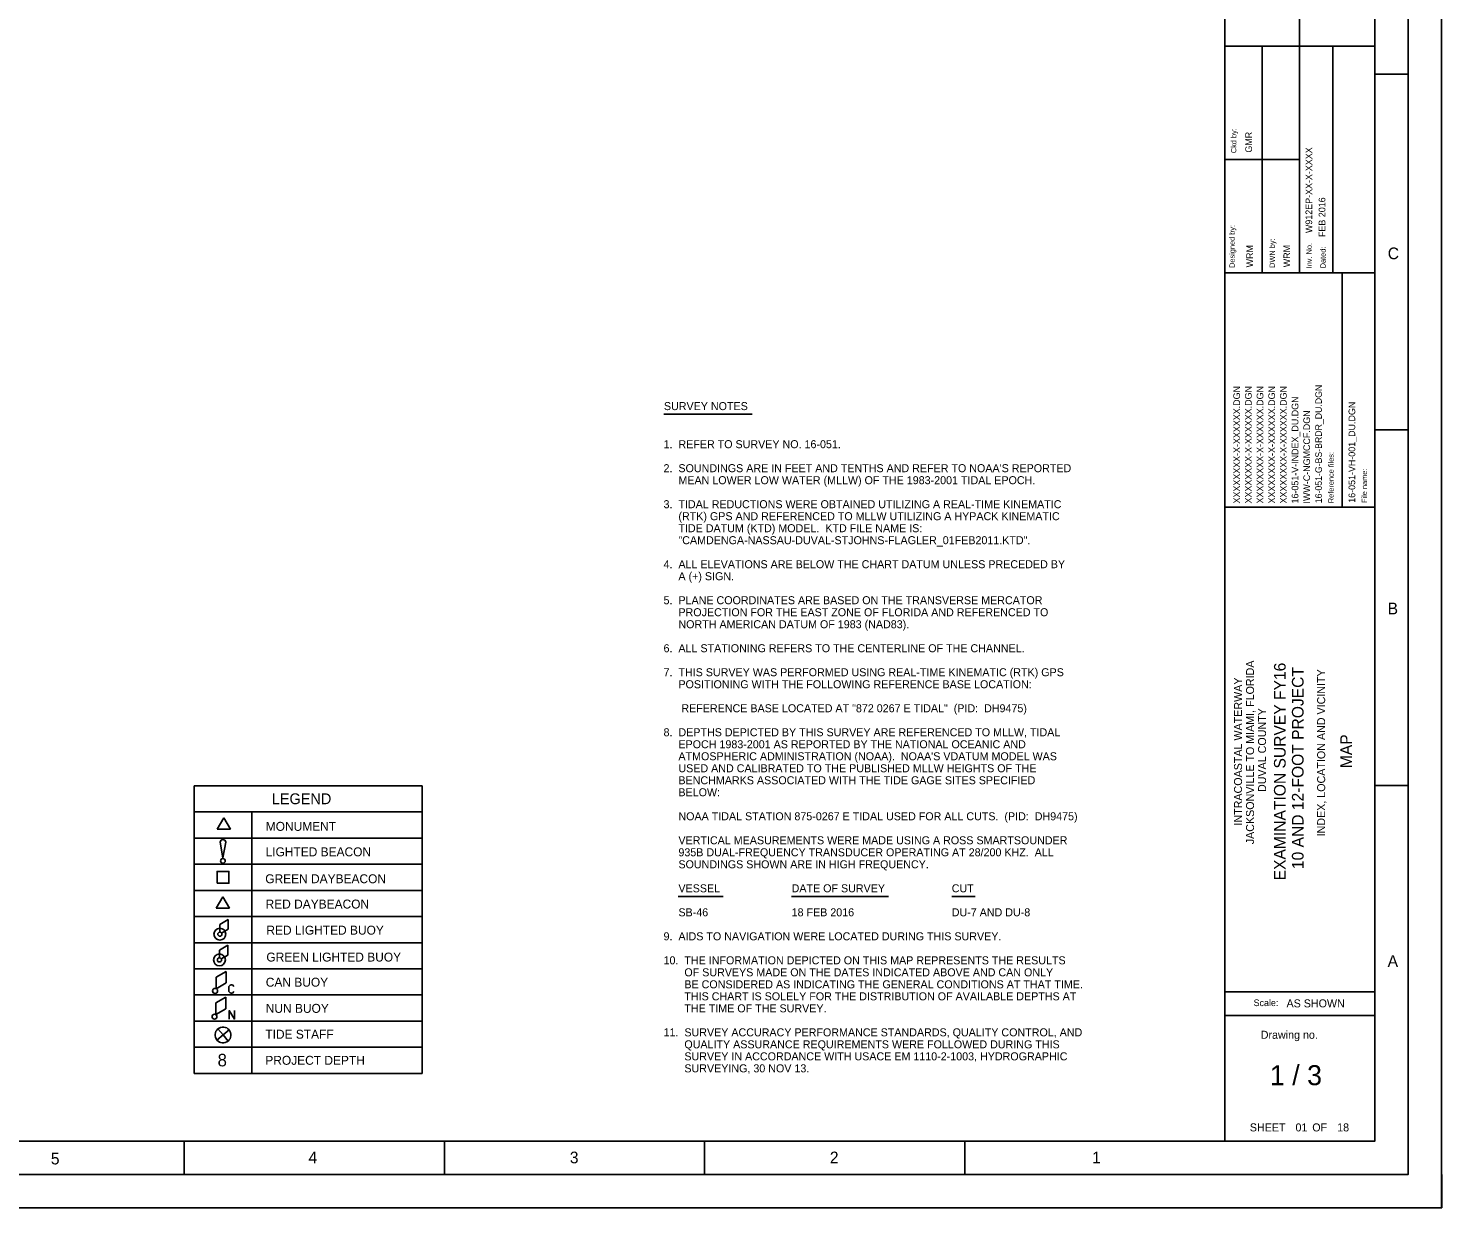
# Model space of a CAD drawing. Extents: x 464090 to 640095, y 2137521 to 2273520.
# Drawn here: x 555342 to 640095, y 2137521 to 2208273 of the extents above; entities that cross this region are included whole.
import ezdxf

# ---------------------------------------------------------------- set-up
doc = ezdxf.new("R2010")
doc.units = 0
for name, color, linetype in [('G-ANNO-NPLT', 7, 'Continuous'), ('G-ANNO-TEXT-DRWG', 7, 'Continuous'), ('G-ANNO-TEXT-PROJ', 7, 'Continuous'), ('G-ANNO-TEXT-TTLB', 7, 'Continuous'), ('G-ANNO-TTLB', 7, 'Continuous'), ('V-ANNO-LEGN', 7, 'Continuous'), ('V-ANNO-TEXT', 7, 'Continuous')]:
    doc.layers.add(name, color=color, linetype=linetype)

msp = doc.modelspace()

# ---------------------------------------------------------------- linework, layer by layer
at = {"layer": 'G-ANNO-NPLT'}
msp.add_lwpolyline([(464090, 2273520), (640089, 2273520), (640089, 2137521), (464090, 2137521)], close=True, dxfattribs=at)
msp.add_lwpolyline([(640095, 2139521), (640095, 2137521), (638095, 2137521)], dxfattribs=at)
at = {"layer": 'G-ANNO-TTLB'}
for p, q in [((627088, 2269520), (627088, 2141521)), ((631563, 2193607), (631589, 2227990)), ((627057, 2207194), (636089, 2207194)), ((629325, 2193609), (629335, 2207194)), ((633571, 2207194), (633571, 2193607)), ((638089, 2205516), (636089, 2205516)), ((627057, 2200400), (631568, 2200400)), ((627041, 2193607), (636089, 2193607)), ((634117, 2193607), (634117, 2179551)), ((638089, 2184185), (636089, 2184185)), ((627089, 2179551), (636089, 2179551)), ((638089, 2162853), (636089, 2162853)), ((627088, 2150471), (636089, 2150471)), ((627088, 2149044), (636089, 2149044)), ((564690, 2139521), (564690, 2141521)), ((580290, 2139521), (580290, 2141521)), ((595890, 2139521), (595890, 2141521)), ((611490, 2139521), (611490, 2141521))]:
    msp.add_line(p, q, dxfattribs=at)
for points in [[(466090, 2139521), (638089, 2139521), (638089, 2271520), (466090, 2271520)], [(636089, 2269520), (471090, 2269520), (471090, 2141521), (636089, 2141521)]]:
    msp.add_lwpolyline(points, close=True, dxfattribs=at)
at = {"layer": 'V-ANNO-LEGN'}
for p, q in [((565289, 2162832), (565289, 2145576)), ((565289, 2162832), (578955, 2162832)), ((578955, 2162832), (578955, 2145576)), ((565289, 2161264), (578955, 2161263)), ((568749, 2161256), (568749, 2145576)), ((566670, 2160225), (567069, 2160912)), ((567069, 2160912), (567462, 2160227)), ((565289, 2159695), (578955, 2159695)), ((567464, 2160223), (566670, 2160225)), ((567015, 2158505), (566848, 2159454)), ((567182, 2159454), (567015, 2158505)), ((565289, 2158127), (578955, 2158127)), ((565289, 2156558), (578955, 2156558)), ((566611, 2155486), (567011, 2156173)), ((567011, 2156173), (567403, 2155488)), ((567405, 2155484), (566611, 2155486)), ((565289, 2154989), (578955, 2154989)), ((566830, 2154516), (567336, 2154808)), ((566830, 2154057), (566830, 2154516)), ((567336, 2154808), (567336, 2154224)), ((567336, 2154224), (566938, 2153994)), ((565289, 2153420), (578955, 2153420)), ((566806, 2152973), (567312, 2153265)), ((566806, 2152514), (566806, 2152973)), ((567312, 2153265), (567312, 2152681)), ((567312, 2152681), (566914, 2152451)), ((565289, 2151851), (578955, 2151851)), ((566612, 2151353), (567213, 2151701)), ((566613, 2150657), (566612, 2151353)), ((567213, 2151701), (567214, 2151006)), ((565289, 2150283), (578955, 2150283)), ((567214, 2151006), (566613, 2150657)), ((566580, 2149115), (566583, 2149810)), ((567184, 2149460), (566580, 2149115)), ((566583, 2149810), (567186, 2150155)), ((567186, 2150155), (567184, 2149460)), ((565289, 2148714), (578955, 2148714)), ((567018, 2147884), (566653, 2147580)), ((566715, 2148249), (567018, 2147884)), ((567018, 2147884), (567384, 2148187)), ((567322, 2147518), (567018, 2147884)), ((565289, 2147145), (578955, 2147145)), ((565289, 2145576), (578955, 2145576))]:
    msp.add_line(p, q, dxfattribs=at)
msp.add_lwpolyline([(566659, 2156991), (566660, 2157699), (567368, 2157698), (567368, 2156990)], close=True, dxfattribs=at)
for points in [[(567676, 2150796), (567612, 2150880), (567548, 2150896), (567504, 2150896), (567444, 2150880), (567376, 2150796), (567361, 2150684), (567361, 2150624), (567361, 2150584), (567365, 2150548), (567377, 2150484), (567445, 2150405), (567505, 2150389), (567541, 2150389), (567609, 2150405), (567676, 2150485)], [(567387, 2148838), (567389, 2149345), (567702, 2148837), (567705, 2149344)]]:
    msp.add_lwpolyline(points, dxfattribs=at)
for centre, radius in [((567013, 2158324), 143), ((566830, 2153932), 355), ((566830, 2153932), 125), ((566806, 2152389), 355), ((566806, 2152389), 125), ((566541, 2150527), 149), ((566508, 2148984), 149)]:
    msp.add_circle(centre, radius, dxfattribs=at)
for centre, radius, start, end in [((567015, 2159441), 168, 4.64421, 175.35452), ((567018, 2147884), 475, 129.68581, 219.68582), ((567018, 2147884), 475, 39.68564, 129.68577), ((567018, 2147884), 475, 309.6858, 39.68585), ((567018, 2147884), 475, 219.6858, 309.68579)]:
    msp.add_arc(centre, radius, start, end, dxfattribs=at)
at = {"layer": 'V-ANNO-TEXT'}
for p, q in [((593457, 2185129), (598755, 2185129)), ((594304, 2156183), (597004, 2156183)), ((601114, 2156183), (606932, 2156183)), ((610714, 2156183), (612118, 2156183))]:
    msp.add_line(p, q, dxfattribs=at)

# ---------------------------------------------------------------- texts
at = {"layer": 'G-ANNO-TEXT-DRWG'}
for s, height, p in [('GMR', 400, (628718, 2200813)), ('WRM', 400, (628779, 2193930)), ('WRM', 400, (631004, 2193939)), ('XXXXXXXX-X-XXXXXX.DGN', 400, (627999, 2179766)), ('XXXXXXXX-X-XXXXXX.DGN', 400, (628699, 2179766)), ('XXXXXXXX-X-XXXXXX.DGN', 400, (629399, 2179766)), ('XXXXXXXX-X-XXXXXX.DGN', 400, (630099, 2179766)), ('XXXXXXXX-X-XXXXXX.DGN', 400, (630799, 2179766)), ('16-051-V-INDEX_DU.DGN', 400, (631499, 2179766)), ('16-051-VH-001_DU.DGN', 400, (634907, 2179807)), ('IWW-C-NGMCCF.DGN', 400, (632199, 2179766)), ('INDEX, LOCATION AND VICINITY', 480, (633105, 2159797)), ('MAP', 699.8, (634713, 2163889))]:
    msp.add_text(s, height=height, rotation=90, dxfattribs=at).set_placement(p)
for s, height, p in [('1 / 3', 1200, (629792, 2144873)), (' 01          18', 480, (631149, 2142100))]:
    msp.add_text(s, height=height, dxfattribs=at).set_placement(p)
at = {"layer": 'G-ANNO-TEXT-PROJ'}
for s, height, p in [('W912EP-XX-X-XXXX', 400, (632326, 2195987)), ('FEB 2016', 400, (633118, 2195750)), ('16-051-G-BS-BRDR_DU.DGN', 392, (632906, 2179781)), ('JACKSONVILLE TO MIAMI, FLORIDA', 480, (628840, 2159325)), ('EXAMINATION SURVEY FY16', 700, (630736, 2157160)), ('10 AND 12-FOOT PROJECT', 700, (631812, 2157835)), ('INTRACOASTAL WATERWAY', 480, (628120, 2160446)), ('DUVAL COUNTY', 480, (629560, 2162458))]:
    msp.add_text(s, height=height, rotation=90, dxfattribs=at).set_placement(p)
at = {"layer": 'G-ANNO-TEXT-TTLB'}
for s, p in [('Ckd by:', (627780, 2200779)), ('Designed by:', (627682, 2193897)), ('DWN by:', (630090, 2193899)), ('Inv. No.', (632299, 2193870)), ('Dated:', (633132, 2193873)), ('Reference files:', (633614, 2179784)), ('File name:', (635613, 2179794))]:
    msp.add_text(s, height=320, rotation=90, dxfattribs=at).set_placement(p)
for s, height, p in [('Scale:', 400, (628813, 2149616)), ('AS SHOWN', 480, (630787, 2149540)), ('Drawing no.', 480, (629242, 2147656)), ('SHEET         OF', 480, (628588, 2142100))]:
    msp.add_text(s, height=height, dxfattribs=at).set_placement(p)
at = {"layer": 'G-ANNO-TTLB'}
for s, p in [('C', (636859, 2194420)), ('B', (636851, 2173118)), ('A', (636851, 2151969)), ('4', (572143, 2140187)), ('3', (587816, 2140187)), ('2', (603407, 2140187)), ('1', (619133, 2140187)), ('5', (556696, 2140121))]:
    msp.add_text(s, height=700, dxfattribs=at).set_placement(p)
at = {"layer": 'V-ANNO-LEGN'}
for s, height, p in [('LEGEND', 649, (569945, 2161729)), ('MONUMENT', 535.4, (569583, 2160131)), ('LIGHTED BEACON', 535.39, (569572, 2158602)), ('GREEN DAYBEACON', 535.39, (569552, 2156988)), ('RED DAYBEACON', 535.39, (569572, 2155470)), ('RED LIGHTED BUOY', 535.39, (569620, 2153904)), ('GREEN LIGHTED BUOY', 535.39, (569620, 2152290)), ('CAN BUOY', 535.4, (569583, 2150782)), ('NUN BUOY', 535.4, (569583, 2149213)), ('TIDE STAFF', 535.4, (569556, 2147663)), ('8', 751, (566694, 2146003)), ('PROJECT DEPTH', 535.39, (569556, 2146097))]:
    msp.add_text(s, height=height, rotation=360, dxfattribs=at).set_placement(p)
at = {"layer": 'V-ANNO-TEXT'}
for s, p in [('SURVEY NOTES', (593456, 2185368)), ('1.  REFER TO SURVEY NO. 16-051.', (593434, 2183083)), ("2.  SOUNDINGS ARE IN FEET AND TENTHS AND REFER TO NOAA'S REPORTED", (593434, 2181643)), ('     MEAN LOWER LOW WATER (MLLW) OF THE 1983-2001 TIDAL EPOCH.', (593434, 2180923)), ('3.  TIDAL REDUCTIONS WERE OBTAINED UTILIZING A REAL-TIME KINEMATIC', (593434, 2179483)), ('     (RTK) GPS AND REFERENCED TO MLLW UTILIZING A HYPACK KINEMATIC', (593434, 2178763)), ('     TIDE DATUM (KTD) MODEL.  KTD FILE NAME IS:', (593434, 2178043)), ('     "CAMDENGA-NASSAU-DUVAL-STJOHNS-FLAGLER_01FEB2011.KTD".', (593434, 2177323)), ('4.  ALL ELEVATIONS ARE BELOW THE CHART DATUM UNLESS PRECEDED BY', (593434, 2175883)), ('     A (+) SIGN.', (593434, 2175163)), ('5.  PLANE COORDINATES ARE BASED ON THE TRANSVERSE MERCATOR', (593434, 2173723)), ('     PROJECTION FOR THE EAST ZONE OF FLORIDA AND REFERENCED TO', (593434, 2173003)), ('     NORTH AMERICAN DATUM OF 1983 (NAD83).', (593434, 2172283)), ('6.  ALL STATIONING REFERS TO THE CENTERLINE OF THE CHANNEL.', (593434, 2170843)), ('7.  THIS SURVEY WAS PERFORMED USING REAL-TIME KINEMATIC (RTK) GPS', (593434, 2169403)), ('     POSITIONING WITH THE FOLLOWING REFERENCE BASE LOCATION:', (593434, 2168683)), ('      REFERENCE BASE LOCATED AT "872 0267 E TIDAL"  (PID:  DH9475)', (593434, 2167243)), ('8.  DEPTHS DEPICTED BY THIS SURVEY ARE REFERENCED TO MLLW, TIDAL', (593434, 2165803)), ('     EPOCH 1983-2001 AS REPORTED BY THE NATIONAL OCEANIC AND', (593434, 2165083)), ("     ATMOSPHERIC ADMINISTRATION (NOAA).  NOAA'S VDATUM MODEL WAS", (593434, 2164363)), ('     USED AND CALIBRATED TO THE PUBLISHED MLLW HEIGHTS OF THE ', (593434, 2163643)), ('     BENCHMARKS ASSOCIATED WITH THE TIDE GAGE SITES SPECIFIED', (593434, 2162923)), ('     BELOW:', (593434, 2162203)), ('     NOAA TIDAL STATION 875-0267 E TIDAL USED FOR ALL CUTS.  (PID:  DH9475)', (593434, 2160763)), ('     VERTICAL MEASUREMENTS WERE MADE USING A ROSS SMARTSOUNDER', (593434, 2159323)), ('     935B DUAL-FREQUENCY TRANSDUCER OPERATING AT 28/200 KHZ.  ALL', (593434, 2158603)), ('     SOUNDINGS SHOWN ARE IN HIGH FREQUENCY.', (593434, 2157883)), ('     VESSEL', (593434, 2156443)), ('DATE OF SURVEY', (601114, 2156443)), ('CUT', (610714, 2156443)), ('     SB-46', (593434, 2155003)), ('18 FEB 2016', (601114, 2155003)), ('DU-7 AND DU-8', (610714, 2155003)), ('9.  AIDS TO NAVIGATION WERE LOCATED DURING THIS SURVEY.', (593434, 2153563)), ('10.  THE INFORMATION DEPICTED ON THIS MAP REPRESENTS THE RESULTS', (593434, 2152123)), ('       OF SURVEYS MADE ON THE DATES INDICATED ABOVE AND CAN ONLY', (593434, 2151403)), ('       BE CONSIDERED AS INDICATING THE GENERAL CONDITIONS AT THAT TIME.', (593434, 2150683)), ('       THIS CHART IS SOLELY FOR THE DISTRIBUTION OF AVAILABLE DEPTHS AT', (593434, 2149963)), ('       THE TIME OF THE SURVEY.', (593434, 2149243)), ('11.  SURVEY ACCURACY PERFORMANCE STANDARDS, QUALITY CONTROL, AND', (593434, 2147803)), ('       SURVEY IN ACCORDANCE WITH USACE EM 1110-2-1003, HYDROGRAPHIC', (593434, 2146363)), ('       QUALITY ASSURANCE REQUIREMENTS WERE FOLLOWED DURING THIS', (593434, 2147083)), ('       SURVEYING, 30 NOV 13.    ', (593434, 2145643))]:
    msp.add_text(s, height=480, dxfattribs=at).set_placement(p)

doc.saveas('drawing.dxf')
